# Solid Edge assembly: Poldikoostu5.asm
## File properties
Author: Türk
Template: Iso Assembly.asm
Last saved by: Türk
Revision: 10
Application: Solid Edge
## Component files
Polt59x20.par
Mutter.par
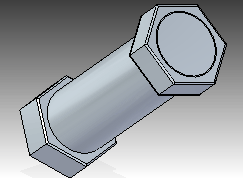
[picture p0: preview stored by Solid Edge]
